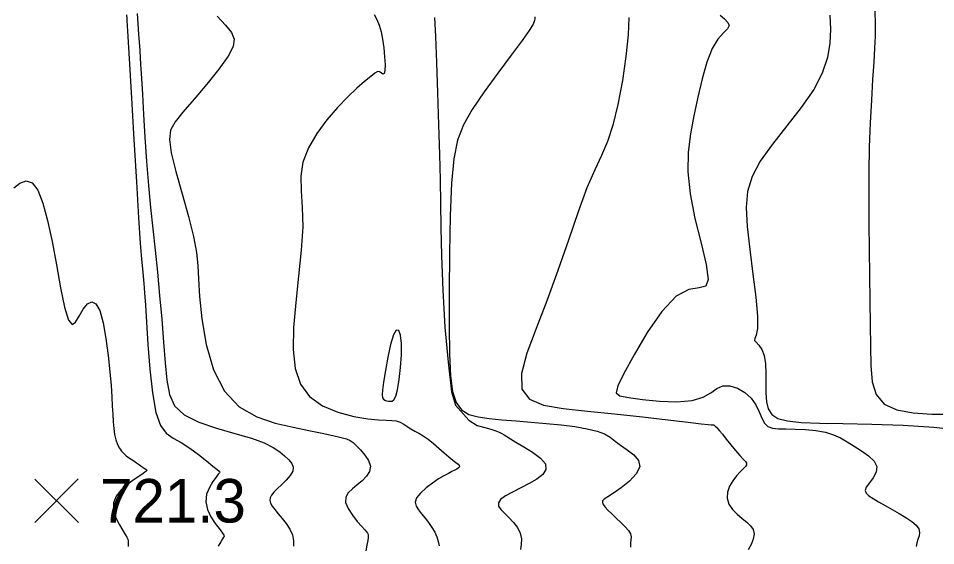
# Model space of a CAD drawing. Extents: x 2566142 to 2571431, y 418755 to 421584.
# Drawn here: x 2566568.3 to 2566884.2, y 419737.1 to 419918.7 of the extents above; entities that cross this region are included whole.
import ezdxf

# ---------------------------------------------------------------- set-up
doc = ezdxf.new("R2010")
doc.units = 0
for name, color, linetype in [('Contour_ADS_Major', 7, 'Continuous'), ('Contour_ADS_Minor', 7, 'Continuous'), ('Contour_ADS_Spot_Elevation', 7, 'Continuous')]:
    doc.layers.add(name, color=color, linetype=linetype)

# ---------------------------------------------------------------- blocks, each defined once
blk = doc.blocks.new('S750')
at = {"layer": 'Contour_ADS_Spot_Elevation'}
for p, q in [((-0.5, 0.498), (0.5, -0.498)), ((-0.498, -0.5), (0.498, 0.5))]:
    blk.add_line(p, q, dxfattribs=at)

msp = doc.modelspace()

# ---------------------------------------------------------------- linework, layer by layer
at = {"layer": 'Contour_ADS_Major'}
for points in [[(2566690.79, 419920.04), (2566691.79, 419918.22), (2566692.59, 419916.27), (2566693.22, 419914.07), (2566693.73, 419911.5), (2566694.14, 419908.52), (2566694.44, 419905.46), (2566694.58, 419902.71), (2566694.52, 419900.7), (2566694.26, 419899.69), (2566693.84, 419899.49), (2566693.35, 419899.76), (2566692.88, 419900.15), (2566692.45, 419900.37), (2566691.9, 419900.27), (2566691.03, 419899.74), (2566689.64, 419898.67), (2566687.56, 419896.97), (2566684.89, 419894.62), (2566681.73, 419891.62), (2566678.24, 419887.97), (2566674.58, 419883.69), (2566671.1, 419878.98), (2566668.2, 419874.04), (2566666.28, 419869.11), (2566665.57, 419864.28), (2566665.68, 419859.25), (2566666.08, 419853.57), (2566666.23, 419846.84), (2566665.74, 419838.79), (2566664.81, 419829.9), (2566663.8, 419820.83), (2566663.06, 419812.22), (2566662.92, 419804.61), (2566663.64, 419798.13), (2566665.44, 419792.75), (2566668.55, 419788.48), (2566673.04, 419785.28), (2566678.35, 419783.04), (2566683.79, 419781.57), (2566688.62, 419780.74), (2566692.31, 419780.36), (2566694.99, 419780.25), (2566696.94, 419780.21), (2566698.45, 419780.03), (2566699.78, 419779.57), (2566701.03, 419778.88), (2566702.24, 419778.08), (2566703.48, 419777.28), (2566704.8, 419776.53), (2566706.21, 419775.77), (2566707.75, 419774.89), (2566709.43, 419773.75), (2566711.25, 419772.3), (2566713.12, 419770.67), (2566714.93, 419769.06), (2566716.57, 419767.63), (2566717.94, 419766.54), (2566719, 419765.75), (2566719.74, 419765.16), (2566720.14, 419764.69), (2566720.18, 419764.27), (2566719.91, 419763.87), (2566719.36, 419763.47), (2566718.58, 419763.05), (2566717.6, 419762.58), (2566716.38, 419761.98), (2566714.88, 419761.17), (2566713.04, 419760.06), (2566710.89, 419758.61), (2566708.69, 419756.94), (2566706.76, 419755.19), (2566705.45, 419753.52), (2566705, 419752.04), (2566705.27, 419750.7), (2566706.06, 419749.41), (2566707.16, 419748.06), (2566708.38, 419746.58)], [(2566847.82, 419919.75), (2566848.03, 419914.97), (2566847.8, 419910.14), (2566846.95, 419905.14), (2566845.18, 419899.85), (2566842.22, 419894.15), (2566837.95, 419888), (2566832.95, 419881.64), (2566827.98, 419875.37), (2566823.79, 419869.51), (2566820.97, 419864.23), (2566819.44, 419859.1), (2566818.95, 419853.53), (2566819.28, 419846.96), (2566820.16, 419839.06), (2566821.28, 419830.6), (2566822.31, 419822.62), (2566822.91, 419816.14), (2566822.87, 419811.92), (2566822.44, 419809.57), (2566821.98, 419808.42), (2566821.87, 419807.79), (2566822.36, 419807.11), (2566823.27, 419806.12), (2566824.29, 419804.65), (2566825.14, 419802.54), (2566825.6, 419799.7), (2566825.74, 419796.37), (2566825.73, 419792.88), (2566825.72, 419789.54), (2566825.9, 419786.62), (2566826.49, 419784.19)], [(2566826.49, 419784.19), (2566827.74, 419782.27), (2566829.89, 419780.89), (2566833.19, 419780.02), (2566837.87, 419779.54), (2566844.15, 419779.3), (2566852.25, 419779.15), (2566862.19, 419778.94), (2566873.02, 419778.56), (2566883.61, 419777.92), (2566892.81, 419776.91)], [(2566708.38, 419746.58), (2566709.6, 419745), (2566710.74, 419743.36), (2566711.71, 419741.71), (2566712.44, 419740.09), (2566712.93, 419738.53), (2566713.24, 419737.04)]]:
    msp.add_lwpolyline(points, dxfattribs=at)
at = {"layer": 'Contour_ADS_Minor'}
for points in [[(2566863.32, 419921.25), (2566863.41, 419916.64), (2566863.36, 419912.58), (2566863.18, 419908.44), (2566862.89, 419903.6), (2566862.5, 419897.59), (2566862.07, 419890.53), (2566861.67, 419882.69), (2566861.36, 419874.34), (2566861.19, 419865.73), (2566861.14, 419856.93), (2566861.19, 419848.03), (2566861.29, 419839.06), (2566861.43, 419830.13), (2566861.57, 419821.45), (2566861.69, 419813.23), (2566861.76, 419805.71), (2566861.85, 419799.11), (2566862.34, 419793.53), (2566863.71, 419789.08), (2566866.43, 419785.85), (2566870.8, 419783.84), (2566876.46, 419782.82), (2566882.87, 419782.42), (2566889.5, 419782.33)], [(2566605.58, 419919.89), (2566605.64, 419918.66), (2566605.67, 419917.81), (2566605.71, 419917.19), (2566605.74, 419916.75), (2566605.76, 419916.44), (2566605.79, 419916), (2566605.88, 419914.41), (2566606.11, 419910.46), (2566606.54, 419902.92), (2566607.23, 419891.17), (2566608.06, 419876.91), (2566608.93, 419862.41), (2566609.7, 419849.96), (2566610.29, 419841.28), (2566610.71, 419835.79), (2566611.02, 419832.38), (2566611.28, 419829.92), (2566611.52, 419827.37), (2566611.78, 419824.18), (2566612.08, 419819.88), (2566612.45, 419814.01), (2566612.92, 419806.38), (2566613.56, 419797.89), (2566614.45, 419789.68), (2566615.66, 419782.93), (2566617.26, 419778.45), (2566619.24, 419775.78)], [(2566609.2, 419920.29), (2566609.72, 419913.27), (2566610.11, 419907.64), (2566610.41, 419902.83), (2566610.69, 419898.05)], [(2566636.77, 419919.39), (2566639.64, 419916.28), (2566641.66, 419913.8), (2566642.62, 419911.56), (2566642.32, 419909.03), (2566640.57, 419905.68), (2566637.34, 419901.18), (2566633.18, 419896.01), (2566628.82, 419890.86), (2566624.99, 419886.41), (2566622.26, 419883.06), (2566620.71, 419880.21), (2566620.3, 419876.94), (2566620.95, 419872.36), (2566622.55, 419865.9), (2566624.69, 419858.26), (2566626.88, 419850.45), (2566628.65, 419843.51), (2566629.66, 419838.09), (2566630.1, 419833.54), (2566630.33, 419828.82), (2566630.67, 419822.91), (2566631.47, 419815.17), (2566632.99, 419806.37), (2566635.5, 419797.68), (2566639.24, 419790.23), (2566644.35, 419784.91), (2566650.39, 419781.43), (2566656.77, 419779.26), (2566662.92, 419777.85), (2566668.35, 419776.72), (2566672.94, 419775.78), (2566676.64, 419775), (2566679.42, 419774.37), (2566681.29, 419773.85), (2566682.56, 419773.3), (2566683.57, 419772.59), (2566684.68, 419771.54), (2566686.12, 419770.08), (2566687.66, 419768.3), (2566688.92, 419766.36), (2566689.54, 419764.43), (2566689.26, 419762.64), (2566688.23, 419760.99), (2566686.72, 419759.46), (2566685, 419758.04), (2566683.32, 419756.68), (2566681.93, 419755.29), (2566681.08, 419753.75), (2566681.01, 419751.95), (2566681.85, 419749.83), (2566683.33, 419747.58), (2566685.03, 419745.45), (2566686.56, 419743.71), (2566687.61, 419742.52), (2566688.23, 419741.81), (2566688.54, 419741.41), (2566688.69, 419741.18), (2566688.78, 419740.95), (2566688.81, 419740.58), (2566688.77, 419739.92), (2566688.62, 419738.82), (2566688.36, 419737.22), (2566687.91, 419735.29)], [(2566711.67, 419918.96), (2566711.92, 419912.41), (2566712.26, 419903.47), (2566712.65, 419892.97), (2566713.04, 419882.04), (2566713.35, 419871.8), (2566713.54, 419863.02), (2566713.66, 419854.98), (2566713.8, 419846.62), (2566714.03, 419836.86), (2566714.44, 419825.08), (2566715.16, 419812.38), (2566716.34, 419800.32), (2566717.42, 419790.02), (2566718.81, 419785.42), (2566723.39, 419780.27), (2566726.3, 419778.5), (2566728.95, 419777.72), (2566731.06, 419777.15), (2566732.68, 419776.63), (2566733.9, 419776.14), (2566734.83, 419775.68), (2566735.6, 419775.21), (2566736.48, 419774.63), (2566737.73, 419773.83), (2566739.66, 419772.68), (2566742.38, 419771.12), (2566745.41, 419769.25), (2566748.1, 419767.24), (2566749.79, 419765.23), (2566750.01, 419763.35), (2566748.94, 419761.61), (2566746.91, 419759.99), (2566744.27, 419758.44), (2566741.37, 419756.97), (2566738.52, 419755.56), (2566736.07, 419754.24), (2566734.35, 419753), (2566733.6, 419751.86), (2566733.7, 419750.73), (2566734.48, 419749.55), (2566735.72, 419748.25), (2566737.22, 419746.76), (2566738.78, 419745.09), (2566740.15, 419743.29), (2566741.13, 419741.38), (2566741.54, 419739.42), (2566741.51, 419737.5), (2566741.24, 419735.74)], [(2566746.2, 419919.17), (2566746.22, 419918.65), (2566746.09, 419917.95), (2566745.56, 419916.72), (2566744.25, 419914.54), (2566741.8, 419911.02), (2566738.02, 419905.95), (2566733.43, 419899.84), (2566728.72, 419893.39), (2566724.59, 419887.3), (2566721.55, 419881.98), (2566719.53, 419876.67), (2566718.26, 419870.31), (2566717.49, 419861.86), (2566717.01, 419850.67), (2566716.74, 419837.77), (2566716.63, 419824.6), (2566716.65, 419812.62), (2566716.78, 419802.97), (2566717.14, 419795.61), (2566717.86, 419790.19), (2566719.09, 419786.39), (2566720.95, 419783.86)], [(2566778.59, 419918.99), (2566778.33, 419913.01), (2566777.55, 419905.52), (2566776.33, 419897.22), (2566774.79, 419889.03), (2566773.04, 419881.84), (2566771.16, 419876.23), (2566769.1, 419871.47), (2566766.78, 419866.52), (2566764.13, 419860.29), (2566761.09, 419852.06), (2566757.73, 419842.3), (2566754.12, 419831.82), (2566750.35, 419821.43), (2566746.6, 419811.82), (2566743.45, 419803.37), (2566741.59, 419796.34), (2566741.7, 419791.02), (2566744.29, 419787.54), (2566749.16, 419785.48), (2566755.94, 419784.3), (2566764.27, 419783.44), (2566773.65, 419782.47), (2566783.23, 419781.41), (2566792, 419780.39), (2566798.99, 419779.57), (2566803.5, 419779.03), (2566805.92, 419778.75), (2566806.92, 419778.65), (2566807.2, 419778.64), (2566807.32, 419778.67), (2566807.41, 419778.71), (2566807.49, 419778.73), (2566807.59, 419778.72), (2566807.73, 419778.66), (2566807.91, 419778.54), (2566808.12, 419778.38), (2566808.38, 419778.16), (2566808.69, 419777.88), (2566809.13, 419777.43), (2566809.79, 419776.67), (2566810.78, 419775.47), (2566812.12, 419773.77), (2566813.69, 419771.79), (2566815.3, 419769.8), (2566816.76, 419768.1), (2566817.91, 419766.88), (2566818.7, 419766.05), (2566819.11, 419765.45), (2566819.11, 419764.92), (2566818.69, 419764.3), (2566817.92, 419763.5), (2566816.89, 419762.47), (2566815.67, 419761.13), (2566814.39, 419759.45), (2566813.25, 419757.52), (2566812.49, 419755.46), (2566812.35, 419753.39), (2566812.98, 419751.42), (2566814.22, 419749.57), (2566815.82, 419747.9), (2566817.54, 419746.42), (2566819.15, 419745.13), (2566820.48, 419743.92), (2566821.39, 419742.64), (2566821.73, 419741.15), (2566821.41, 419739.37), (2566820.65, 419737.45), (2566819.69, 419735.63)], [(2566810.04, 419919.77), (2566811.54, 419918.46), (2566812.68, 419917.28), (2566813.08, 419916.18), (2566812.48, 419915.09), (2566811.09, 419913.67), (2566809.25, 419911.51), (2566807.27, 419908.24), (2566805.43, 419903.59), (2566803.78, 419897.88), (2566802.29, 419891.57), (2566800.95, 419885.13), (2566799.8, 419878.87), (2566799.02, 419872.56), (2566798.88, 419865.82), (2566799.62, 419858.27), (2566801.31, 419849.79), (2566803.41, 419841.27), (2566805.18, 419833.86), (2566805.92, 419828.71), (2566805.06, 419826.47), (2566802.74, 419825.92), (2566799.24, 419825.33), (2566794.85, 419822.99), (2566789.91, 419817.71), (2566784.91, 419810.49), (2566780.37, 419802.85), (2566776.82, 419796.33), (2566774.7, 419792.07), (2566774.2, 419789.75), (2566775.43, 419788.65), (2566778.48, 419788.06), (2566783.29, 419787.43), (2566789.13, 419786.88), (2566795.1, 419786.65), (2566800.31, 419787.04), (2566804.09, 419788.17), (2566806.75, 419789.7), (2566808.83, 419791.17), (2566810.89, 419792.1), (2566813.32, 419792.13), (2566815.96, 419791.32), (2566818.52, 419789.84), (2566820.7, 419787.86), (2566822.27, 419785.56), (2566823.39, 419783.19), (2566824.31, 419781), (2566825.26, 419779.27), (2566826.46, 419778.16), (2566828.03, 419777.59), (2566830.06, 419777.36), (2566832.66, 419777.29), (2566835.84, 419777.21), (2566839.37, 419777.04), (2566842.94, 419776.71), (2566846.23, 419776.14), (2566849.02, 419775.28), (2566851.45, 419774.16), (2566853.73, 419772.83), (2566856.09, 419771.34), (2566858.64, 419769.73), (2566861.08, 419768.02), (2566862.99, 419766.21), (2566863.97, 419764.32), (2566863.75, 419762.38), (2566862.72, 419760.48), (2566861.4, 419758.72), (2566860.32, 419757.23)], [(2566610.69, 419898.05), (2566611, 419892.49), (2566611.39, 419885.6), (2566611.88, 419877.7), (2566612.45, 419869.36), (2566613.1, 419861.15), (2566613.82, 419853.48), (2566614.59, 419846.17), (2566615.39, 419838.89), (2566616.19, 419831.31), (2566616.96, 419823.25), (2566617.69, 419815.03), (2566618.33, 419807.13), (2566618.88, 419800.02), (2566619.39, 419794.05), (2566620.29, 419789.19), (2566622.12, 419785.26), (2566625.4, 419782.11), (2566630.43, 419779.58), (2566636.55, 419777.51), (2566642.9, 419775.74), (2566648.58, 419774.12), (2566652.92, 419772.52), (2566656.05, 419770.94), (2566658.3, 419769.42), (2566660, 419768), (2566661.4, 419766.68), (2566662.44, 419765.42), (2566662.97, 419764.13), (2566662.83, 419762.75), (2566661.96, 419761.23), (2566660.57, 419759.65), (2566658.98, 419758.1), (2566657.46, 419756.7), (2566656.28, 419755.51), (2566655.47, 419754.49), (2566655.02, 419753.57), (2566654.93, 419752.67), (2566655.18, 419751.72), (2566655.76, 419750.67), (2566656.63, 419749.48), (2566657.77, 419748.09), (2566659.13, 419746.47), (2566660.53, 419744.67), (2566661.78, 419742.75), (2566662.68, 419740.76), (2566663.09, 419738.78), (2566663.1, 419736.88)], [(2566566.71, 419860.27), (2566568.82, 419861.9), (2566570.99, 419862.72), (2566573.09, 419862.06), (2566575.01, 419859.45), (2566576.76, 419855.02), (2566578.38, 419849.05), (2566579.92, 419841.85), (2566581.41, 419833.82), (2566582.85, 419825.9), (2566584.23, 419819.18), (2566585.54, 419814.71), (2566586.79, 419813.21), (2566588.01, 419814.02), (2566589.26, 419816.14), (2566590.6, 419818.53), (2566592.05, 419820.31), (2566593.55, 419821.03), (2566595.02, 419820.39), (2566596.36, 419818.04), (2566597.52, 419813.86), (2566598.47, 419808.43), (2566599.23, 419802.53), (2566599.8, 419796.92), (2566600.2, 419792.22), (2566600.47, 419788.36), (2566600.65, 419785.14), (2566600.8, 419782.33), (2566600.95, 419779.76), (2566601.16, 419777.41), (2566601.44, 419775.31), (2566601.85, 419773.48), (2566602.41, 419771.95), (2566603.08, 419770.68), (2566603.83, 419769.63), (2566604.63, 419768.78), (2566605.42, 419768.07), (2566606.24, 419767.45), (2566607.1, 419766.86), (2566608.03, 419766.25), (2566609.03, 419765.57), (2566610.03, 419764.88), (2566610.93, 419764.24), (2566611.66, 419763.72), (2566612.14, 419763.38), (2566612.41, 419763.18), (2566612.52, 419763.07), (2566612.55, 419763), (2566612.54, 419762.92), (2566612.44, 419762.81)], [(2566720.95, 419783.86), (2566723.47, 419782.3), (2566726.63, 419781.4), (2566730.43, 419780.87), (2566734.85, 419780.43), (2566739.73, 419780.02), (2566744.87, 419779.61), (2566750.09, 419779.17), (2566755.19, 419778.67), (2566759.97, 419778.08), (2566764.18, 419777.37), (2566767.62, 419776.54), (2566770.15, 419775.54), (2566772.07, 419774.39), (2566773.78, 419773.09), (2566775.67, 419771.66), (2566777.97, 419770.09), (2566780.25, 419768.36), (2566781.9, 419766.42), (2566782.31, 419764.23), (2566781.1, 419761.81), (2566778.73, 419759.33), (2566775.88, 419757.04), (2566773.21, 419755.18), (2566771.28, 419753.9), (2566770.1, 419753.07), (2566769.52, 419752.49), (2566769.44, 419751.93), (2566769.74, 419751.24), (2566770.39, 419750.36), (2566771.36, 419749.29), (2566772.65, 419748.03), (2566774.2, 419746.6), (2566775.83, 419745.09), (2566777.32, 419743.6), (2566778.46, 419742.26), (2566779.09, 419741.13), (2566779.31, 419740.11), (2566779.28, 419739.1), (2566779.17, 419737.94), (2566779.06, 419736.57)], [(2566619.24, 419775.78), (2566621.6, 419774.09), (2566624.31, 419772.59), (2566627.32, 419770.65), (2566630.36, 419768.42), (2566633.13, 419766.24), (2566635.32, 419764.45), (2566636.71, 419763.3), (2566637.43, 419762.71), (2566637.69, 419762.48), (2566637.73, 419762.42), (2566637.69, 419762.38), (2566637.54, 419762.17), (2566637.15, 419761.66), (2566636.4, 419760.7), (2566635.28, 419759.17), (2566634.07, 419757.15), (2566633.13, 419754.79), (2566632.83, 419752.22), (2566633.41, 419749.56), (2566634.62, 419747.01), (2566636.08, 419744.74), (2566637.42, 419742.94), (2566638.34, 419741.73), (2566638.86, 419741.03), (2566639.11, 419740.66), (2566639.17, 419740.46), (2566639.14, 419740.28), (2566638.99, 419739.97), (2566638.64, 419739.38), (2566638.05, 419738.38), (2566637.16, 419736.9)], [(2566612.44, 419762.81), (2566612.24, 419762.63), (2566611.87, 419762.37), (2566611.29, 419761.98), (2566610.44, 419761.41), (2566609.26, 419760.61), (2566607.68, 419759.5), (2566605.7, 419758.04), (2566603.67, 419756.25), (2566601.97, 419754.15), (2566601.02, 419751.79), (2566601.08, 419749.21), (2566601.9, 419746.62), (2566603.09, 419744.24), (2566604.27, 419742.28), (2566605.13, 419740.92), (2566605.67, 419739.99), (2566605.96, 419739.29), (2566606.09, 419738.61), (2566606.13, 419737.76), (2566606.12, 419736.79)], [(2566860.32, 419757.23), (2566859.92, 419756.07), (2566860.23, 419755.13), (2566861.15, 419754.26), (2566862.64, 419753.32), (2566864.58, 419752.19), (2566866.84, 419750.9), (2566869.26, 419749.53), (2566871.69, 419748.13), (2566873.97, 419746.77), (2566875.95, 419745.44), (2566877.48, 419744.15), (2566878.42, 419742.9), (2566878.69, 419741.67), (2566878.49, 419740.46), (2566878.08, 419739.24), (2566877.73, 419738.01), (2566877.55, 419736.75)]]:
    msp.add_lwpolyline(points, dxfattribs=at)
msp.add_lwpolyline([(2566694.07, 419787.55), (2566694.54, 419787.22), (2566695.12, 419786.99), (2566695.76, 419786.86), (2566696.41, 419786.8), (2566697.04, 419786.88), (2566697.64, 419787.35), (2566698.24, 419788.54), (2566698.83, 419790.79), (2566699.43, 419794.26), (2566699.93, 419798.48), (2566700.24, 419802.85), (2566700.27, 419806.74), (2566699.92, 419809.6), (2566699.28, 419811.16), (2566698.42, 419811.24), (2566697.45, 419809.64), (2566696.45, 419806.35), (2566695.51, 419802), (2566694.69, 419797.43), (2566694.08, 419793.44), (2566693.74, 419790.66), (2566693.64, 419788.97), (2566693.76, 419788.04), (2566694.07, 419787.55)], close=True, dxfattribs=at)

# ---------------------------------------------------------------- block references
at = {"layer": 'Contour_ADS_Spot_Elevation', "xscale": 15, "yscale": 15}
msp.add_blockref('S750', (2566581.45, 419752.54), dxfattribs=at)

# ---------------------------------------------------------------- texts
at = {"layer": 'Contour_ADS_Spot_Elevation'}
msp.add_text('721.3', height=15, dxfattribs=at).set_placement((2566596.45, 419745.04))

doc.saveas('drawing.dxf')
